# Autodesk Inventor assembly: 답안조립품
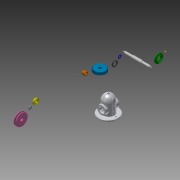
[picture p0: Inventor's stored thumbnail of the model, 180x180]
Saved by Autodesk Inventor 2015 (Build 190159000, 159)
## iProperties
Created: 2019-11
Part Number: 답안조립품
Document SubType Name: Assembly
Designer: now
Author: now
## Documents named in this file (14)
- C:\Users\now\Desktop\지용\491104V1037\491104V1037\답안조립품.iam
- C:\Users\now\Desktop\지용\491104V1037\491104V1037\V-벨트풀리.ipt
- V-벨트풀리.ipt
- C:\Users\now\Desktop\지용\491104V1037\491104V1037\너트 M12x1.25.ipt
- C:\Users\now\Desktop\지용\491104V1037\491104V1037\베어링 6203.ipt
- C:\Users\now\Desktop\지용\491104V1037\491104V1037\본체.ipt
- C:\Users\now\Desktop\지용\491104V1037\491104V1037\볼트 M4.ipt
- C:\Users\now\Desktop\지용\491104V1037\491104V1037\부시.ipt
- C:\Users\now\Desktop\지용\491104V1037\491104V1037\스퍼기어.ipt
- C:\Users\now\Desktop\지용\491104V1037\491104V1037\오일 실 26 38 8.ipt
- C:\Users\now\Desktop\지용\491104V1037\491104V1037\와셔 12x24.ipt
- C:\Users\now\Desktop\지용\491104V1037\491104V1037\축.ipt
- C:\Users\now\Desktop\지용\491104V1037\491104V1037\커버.ipt
- C:\Users\now\Desktop\지용\491104V1037\491104V1037\키 5x5x12.ipt
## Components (1 placed, 1 different names)
1. V-벨트풀리:1
